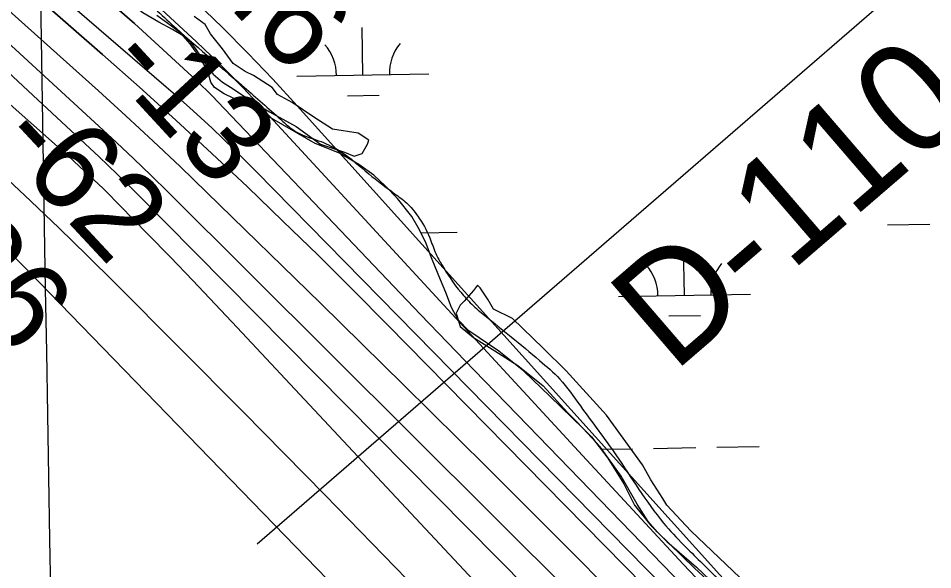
# Model space of a CAD drawing. Extents: x 3887375 to 3925618, y 296674 to 322633.
# Drawn here: x 3896776 to 3897469, y 311546 to 311964 of the extents above; entities that cross this region are included whole.
import ezdxf

# ---------------------------------------------------------------- set-up
doc = ezdxf.new("R2010")
doc.units = 0
for name, color, linetype in [('V-GRID-MAJR', 7, 'Continuous'), ('V-RIVR-EDGE', 7, 'Continuous'), ('V-RIVR-JETY', 7, 'Continuous'), ('V-RIVR-RANG', 7, 'Continuous'), ('V-RIVR-RANG-IDEN', 7, 'Continuous'), ('V-TOPO-DPTH', 7, 'Continuous'), ('V-TOPO-MAJR', 7, 'Continuous'), ('V-TOPO-MINR', 7, 'Continuous'), ('V-TOPO-WATR', 7, 'Continuous'), ('V-WETL-SWMP', 7, 'Continuous')]:
    doc.layers.add(name, color=color, linetype=linetype)

msp = doc.modelspace()

# ---------------------------------------------------------------- linework, layer by layer
at = {"layer": 'V-GRID-MAJR'}
msp.add_spline([(3896958.3310000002, 302197.087), (3896856.111, 308255.118), (3896753.858, 314315.074), (3896651.606, 320375.025), (3896651.573, 320376.956)], degree=3, dxfattribs=at)
at = {"layer": 'V-RIVR-EDGE'}
msp.add_spline([(3896115.8075614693, 312736.3390653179), (3896123.645504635, 312723.7137947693), (3896129.940618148, 312714.38723340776), (3896135.5673755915, 312703.73218250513), (3896139.52488738, 312690.4209747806), (3896139.83521988, 312681.44174761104), (3896138.156107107, 312674.7951886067), (3896136.8243285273, 312674.1334106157), (3896128.5331916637, 312683.1323720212), (3896119.587677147, 312696.45591364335), (3896111.2998293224, 312706.78500910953), (3896107.31189392, 312707.7924767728), (3896104.980870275, 312706.468098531), (3896104.302647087, 312701.14920680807), (3896107.93009214, 312688.8364218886), (3896111.2365153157, 312681.1799284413), (3896123.505720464, 312667.1830971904), (3896140.7481276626, 312647.188328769), (3896160.9586687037, 312617.2101545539), (3896188.4791912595, 312584.8861560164), (3896210.0404228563, 312563.21803064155), (3896237.5798573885, 312538.54230295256), (3896253.5077534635, 312524.8689603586), (3896271.434139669, 312512.5208182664), (3896287.7019695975, 312501.8394550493), (3896298.990841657, 312494.8282943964), (3896306.951911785, 312486.82775579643), (3896325.8306742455, 312456.1878035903), (3896335.7630999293, 312438.53885949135), (3896350.6917509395, 312424.2029166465), (3896373.5880501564, 312404.5267033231), (3896404.790286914, 312381.8371318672), (3896441.9789492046, 312359.46529324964), (3896468.8746954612, 312343.4370814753), (3896491.127306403, 312332.4083840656), (3896500.092555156, 312327.06564680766), (3896508.385336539, 312318.7317524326), (3896515.338116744, 312306.410744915), (3896528.252654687, 312284.43146478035), (3896534.8720791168, 312271.7787460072), (3896552.796820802, 312258.7655368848), (3896583.0105018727, 312239.73630087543), (3896613.555071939, 312220.041175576), (3896639.772595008, 312198.69407207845), (3896665.320939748, 312175.6859455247), (3896698.518377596, 312152.99144051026), (3896718.435853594, 312138.97569728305), (3896746.973710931, 312114.63003633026), (3896768.2056980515, 312094.2928672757), (3896793.746642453, 312068.29193908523), (3896812.6517172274, 312048.29305936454), (3896828.9006351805, 312029.9634252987), (3896844.471329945, 312006.3148995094), (3896867.3569397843, 311982.3157504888), (3896895.8898635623, 311955.9748884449), (3896948.9817541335, 311909.95370177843), (3896976.5220109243, 311885.61050760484), (3896985.1506148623, 311878.6059250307), (3896997.7729100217, 311872.9216093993), (3897005.414602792, 311870.24242930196), (3897020.0279877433, 311862.8905125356), (3897041.600730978, 311845.87785637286), (3897061.1832066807, 311830.8653348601), (3897070.144344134, 311823.8599300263), (3897078.7655477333, 311813.8625458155), (3897087.703661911, 311797.54620255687), (3897092.32952977, 311785.5634843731), (3897096.9636202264, 311776.906101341), (3897111.2115812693, 311756.25366622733), (3897119.502718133, 311747.2547048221), (3897129.4573448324, 311738.5841656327), (3897149.3698872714, 311722.5732213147), (3897170.9401637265, 311704.5629646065), (3897186.2021705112, 311690.5587330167), (3897201.7810878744, 311670.2355423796), (3897228.6250317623, 311633.25771914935), (3897264.7437346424, 311581.62539797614), (3897279.999163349, 311564.96089826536), (3897305.2100410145, 311539.95839288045), (3897328.427362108, 311515.6258880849), (3897360.94246547, 311485.9498237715), (3897388.807033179, 311458.28047218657), (3897419.340913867, 311434.2624111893), (3897433.937853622, 311420.25982411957), (3897454.4916175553, 311394.60376334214), (3897475.043736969, 311368.2826355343), (3897490.6390995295, 311354.61011520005), (3897505.558705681, 311336.61630368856), (3897515.8253093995, 311319.6316043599), (3897527.761158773, 311305.3030618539), (3897546.6736338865, 311288.2969837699), (3897564.6115317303, 311280.6043108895), (3897578.222382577, 311271.25965981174), (3897592.820966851, 311257.92213977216), (3897613.057820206, 311238.5850380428), (3897630.301049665, 311218.9228031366), (3897644.5547665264, 311200.5981026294), (3897648.867835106, 311196.59701106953), (3897654.8517938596, 311195.91714336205), (3897664.8080650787, 311187.91167120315), (3897681.400205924, 311173.90415057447), (3897695.9881008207, 311156.2436948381), (3897728.1624480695, 311123.2431176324), (3897747.7227227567, 311099.2521912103), (3897753.6811914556, 311088.26378453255), (3897756.6674150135, 311085.5961160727), (3897762.6464402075, 311082.9210472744), (3897779.5678255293, 311067.5825703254), (3897798.4712557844, 311046.91862357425), (3897815.3852407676, 311028.5873449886), (3897831.9773816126, 311014.5798243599), (3897852.225746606, 310999.8981918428), (3897867.8194646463, 310985.56060447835), (3897880.750447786, 310970.231994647), (3897893.9999860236, 310949.2494927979), (3897907.5828800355, 310928.59870220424), (3897922.1641968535, 310908.27797834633), (3897948.0310966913, 310879.615959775), (3897967.2613046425, 310856.6234561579), (3897987.8257579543, 310835.2903310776), (3898011.7139018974, 310813.2839163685), (3898048.5560522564, 310785.25983025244), (3898064.4905264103, 310774.24675578), (3898081.4127339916, 310759.240812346), (3898099.651919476, 310738.91104362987), (3898112.91790291, 310724.5792120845), (3898123.186973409, 310708.5921133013), (3898130.8048206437, 310696.2694612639), (3898136.7723342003, 310688.9389232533), (3898147.3846275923, 310677.2739379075), (3898159.9888330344, 310664.2738849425), (3898168.945036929, 310655.2732790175), (3898196.4672040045, 310623.61434751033), (3898206.0753187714, 310609.291560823), (3898214.03474438, 310600.62595519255), (3898230.2828400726, 310581.9637876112), (3898242.212933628, 310565.3075104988), (3898262.438275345, 310541.3149395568), (3898281.6758836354, 310521.3152375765), (3898296.6020678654, 310505.98169418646), (3898340.4085100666, 310470.29206976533), (3898350.024847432, 310459.2946182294), (3898356.9735163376, 310445.310943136), (3898373.552501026, 310425.98288626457), (3898390.138886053, 310409.64763102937), (3898399.4374905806, 310404.6366050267), (3898413.3808749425, 310395.29113168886), (3898421.6744785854, 310387.2897708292), (3898429.9664377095, 310378.6233429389), (3898436.5792840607, 310363.3103560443), (3898463.4437844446, 310334.64587069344), (3898482.3488592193, 310314.646990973), (3898496.60750964, 310298.31749155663), (3898513.1881388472, 310279.6545017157), (3898535.738748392, 310254.6585744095), (3898547.3461755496, 310241.9935217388), (3898560.27222513, 310224.66971081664), (3898576.512920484, 310203.01474159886), (3898592.1041717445, 310187.679553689), (3898611.3376687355, 310166.01718413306), (3898633.549988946, 310138.6943444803), (3898638.1947687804, 310134.3598971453), (3898642.5144154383, 310133.0190737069), (3898652.1447312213, 310127.67469192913), (3898657.787933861, 310123.6703113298), (3898665.4164704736, 310115.6705949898), (3898676.6880750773, 310101.6762305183), (3898685.971878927, 310090.6796012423), (3898692.6093930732, 310085.342619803), (3898699.247729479, 310080.33817187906), (3898707.868110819, 310070.008254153), (3898714.4850684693, 310056.3579348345), (3898718.4442247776, 310043.7117941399), (3898720.43284779, 310041.04659245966), (3898727.404539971, 310036.3738557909), (3898760.272733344, 310015.0103070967), (3898774.2169399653, 310005.9973672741), (3898785.4943003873, 309994.3307374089), (3898801.4041067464, 309973.3416574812), (3898808.685309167, 309959.3571601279), (3898822.609781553, 309942.36341594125), (3898837.8627434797, 309924.70131568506), (3898844.8253908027, 309916.37071034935), (3898858.7490409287, 309899.04443264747), (3898871.351601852, 309885.3793126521), (3898894.5426106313, 309850.4057353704), (3898899.8541020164, 309846.7347105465), (3898908.4851727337, 309840.7277285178), (3898917.1244660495, 309838.0460816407), (3898920.4440453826, 309835.71012443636), (3898928.060248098, 309822.7224053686), (3898935.3513176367, 309812.7283101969), (3898943.639987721, 309802.7317482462), (3898951.916323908, 309787.747183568), (3898962.852105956, 309772.4235072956), (3898972.4585762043, 309757.4356535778), (3898979.0969126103, 309752.4312056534), (3898987.0694943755, 309749.08613626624), (3898990.7174959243, 309745.0866892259), (3899001.9808779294, 309727.76698960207), (3899013.2565938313, 309715.4352927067), (3899031.16653484, 309696.43648031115), (3899044.7601182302, 309680.1086254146), (3899055.6975447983, 309665.4500161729), (3899064.9797041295, 309653.78831986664), (3899074.589463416, 309640.13060020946), (3899085.5400461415, 309630.79252721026), (3899093.846805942, 309628.11170259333), (3899099.1673421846, 309628.09854643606), (3899103.152810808, 309626.09347822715), (3899108.1161457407, 309616.1051388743), (3899114.7429705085, 309606.44522173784), (3899123.683551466, 309591.1264790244), (3899128.318464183, 309582.8016295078), (3899128.3127083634, 309580.47389490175), (3899127.6196844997, 309569.1693999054), (3899127.9439954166, 309565.84324249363), (3899132.921308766, 309561.5079728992), (3899159.7767642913, 309529.18561888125), (3899190.9559777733, 309497.18510900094), (3899204.881272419, 309480.52389832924), (3899212.171519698, 309470.19726964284), (3899224.775725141, 309457.19721667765), (3899244.679222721, 309437.5284036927), (3899252.6411151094, 309429.86039860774), (3899261.9347860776, 309422.8541715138), (3899272.5585911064, 309415.84465538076), (3899279.51877165, 309406.5164494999), (3899287.4740859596, 309396.18817629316), (3899300.0618462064, 309376.5374530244), (3899311.333450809, 309362.5430885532), (3899327.912435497, 309343.21503168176), (3899342.167796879, 309325.55539820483), (3899360.0728043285, 309304.56138471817), (3899377.311100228, 309282.9039487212), (3899414.4504269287, 309240.5800991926), (3899433.3530349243, 309219.5836189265), (3899447.280796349, 309203.92000880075), (3899464.5256703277, 309184.92284092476), (3899479.112742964, 309166.92985167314), (3899493.3697488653, 309149.9352852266)], degree=3, dxfattribs=at)
at = {"layer": 'V-RIVR-JETY'}
for points in [[(3896881.043411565, 311966.0012621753), (3896892.2221385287, 311957.871278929), (3896900.352121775, 311951.7737914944), (3896906.4496092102, 311945.6763040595), (3896910.514600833, 311940.5950645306), (3896917.6283361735, 311929.41633756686), (3896923.7258236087, 311921.28635432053), (3896930.8395589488, 311915.1888668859), (3896938.9695421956, 311910.107627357), (3896951.1645170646, 311901.9776441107), (3896966.4082356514, 311892.8314129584), (3896986.7331937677, 311881.65268599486), (3897005.025656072, 311868.44146321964), (3897023.3181183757, 311862.3439757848), (3897030.431853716, 311859.29523206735), (3897036.5293411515, 311861.32772787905), (3897040.594332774, 311868.44146321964), (3897041.61058068, 311871.49020693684), (3897033.4805974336, 311876.57144646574), (3897014.171887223, 311879.62019018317), (3896999.9444165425, 311888.7664213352), (3896983.68445005, 311899.945148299), (3896972.5057230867, 311906.04263573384), (3896968.440731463, 311911.12387526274), (3896954.2132607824, 311920.2701064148), (3896948.115773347, 311923.31885013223), (3896938.9695421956, 311929.41633756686), (3896930.8395589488, 311940.5950645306), (3896921.693327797, 311951.7737914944), (3896917.6283361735, 311958.88752683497), (3896909.498352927, 311964.9850142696)], [(3897333.2737296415, 311530.03091059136), (3897285.5100780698, 311575.7620663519), (3897267.217615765, 311595.070776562), (3897264.168872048, 311600.15201609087), (3897255.022640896, 311614.3794867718), (3897248.9251534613, 311625.5582137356), (3897221.486460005, 311663.1593862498), (3897190.999022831, 311696.6955671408), (3897173.7228084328, 311713.97178153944), (3897150.3491065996, 311736.3292354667), (3897136.121635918, 311743.4429708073), (3897132.056644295, 311750.5567061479), (3897125.9591568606, 311759.70293729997), (3897123.926661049, 311761.73543311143), (3897120.8779173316, 311757.67044148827), (3897113.7641819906, 311749.54045824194), (3897110.7154382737, 311746.49171452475), (3897107.6666945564, 311740.3942270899), (3897110.7154382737, 311730.2317480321), (3897120.8779173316, 311722.10176478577), (3897137.1378838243, 311711.93928572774), (3897154.4140982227, 311700.760558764), (3897173.7228084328, 311685.5168401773), (3897192.015270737, 311665.1918820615), (3897210.307733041, 311646.89941975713), (3897222.5027079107, 311630.6394532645), (3897234.6976827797, 311611.3307430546), (3897242.827666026, 311595.070776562), (3897255.022640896, 311579.82705797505), (3897267.217615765, 311567.63208310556), (3897289.575069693, 311548.3233728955), (3897309.9000278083, 311529.01466268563)]]:
    msp.add_lwpolyline(points, dxfattribs=at)
at = {"layer": 'V-RIVR-RANG'}
msp.add_line((3897501.5199, 312036.84659999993), (3896957.1909, 311565.5654000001), dxfattribs=at)
at = {"layer": 'V-TOPO-DPTH'}
for points in [[(3897420.1434630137, 311417.2895414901), (3896987.428998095, 311897.46273339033), (3896968.9094085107, 311917.5150554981), (3896950.071898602, 311937.25650301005), (3896930.7575082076, 311956.5316386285), (3896911.125197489, 311975.4958996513), (3896659.026278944, 312213.12816606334)], [(3896546.070862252, 312192.99895366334), (3896840.0793984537, 311936.0956112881), (3896867.8900182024, 311911.4736937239), (3896895.4833059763, 311886.61368441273), (3896922.7505957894, 311861.3965374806), (3896949.8005536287, 311835.94129880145), (3896976.5613031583, 311810.17931244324), (3897003.153895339, 311784.2465513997), (3897029.4942514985, 311758.05762832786), (3897055.66645031, 311731.69793057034), (3897384.504321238, 311397.2828174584)], [(3896546.070862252, 312192.99895366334), (3896840.0793984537, 311936.0956112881), (3896867.8900182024, 311911.4736937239), (3896895.4833059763, 311886.61368441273), (3896922.7505957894, 311861.3965374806), (3896949.8005536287, 311835.94129880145), (3896976.5613031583, 311810.17931244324), (3897003.153895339, 311784.2465513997), (3897029.4942514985, 311758.05762832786), (3897055.66645031, 311731.69793057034), (3897384.504321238, 311397.2828174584)], [(3897412.9777930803, 311396.37510842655), (3897162.005666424, 311655.33049372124), (3897121.360767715, 311697.3852875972), (3897080.7941851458, 311739.5152815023), (3897040.3450767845, 311781.7580754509), (3896999.974284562, 311824.07606942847), (3896927.37578062, 311900.38867008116), (3896923.32426325, 311904.5675344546), (3896919.2211682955, 311908.69413510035), (3896915.040706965, 311912.7423401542), (3896910.808668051, 311916.7382814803), (3896882.6488346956, 311942.8274258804), (3896864.1276609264, 311959.63134587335), (3896845.3793784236, 311976.1723793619), (3896826.2904328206, 311992.3190830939), (3896806.974378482, 312008.20290032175), (3896718.119793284, 312079.7298174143)], [(3896718.119793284, 312079.7298174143), (3896806.974378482, 312008.20290032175), (3896826.2904328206, 311992.3190830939), (3896845.3793784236, 311976.1723793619), (3896864.1276609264, 311959.63134587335), (3896882.6488346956, 311942.8274258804), (3896910.808668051, 311916.7382814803), (3896915.040706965, 311912.7423401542), (3896919.2211682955, 311908.69413510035), (3896923.32426325, 311904.5675344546), (3896927.37578062, 311900.38867008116), (3896999.974284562, 311824.07606942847), (3897040.3450767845, 311781.7580754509), (3897080.7941851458, 311739.5152815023), (3897121.360767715, 311697.3852875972), (3897162.005666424, 311655.33049372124), (3897412.9777930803, 311396.37510842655)], [(3897255.0818033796, 311499.3240481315), (3897192.9470212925, 311561.8939687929), (3897130.583000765, 311624.2332881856), (3897067.875122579, 311686.2267056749), (3897004.938005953, 311747.98952189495), (3896918.9797630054, 311831.8785189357), (3896898.728047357, 311851.39369997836), (3896878.3140194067, 311870.73538092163), (3896857.6565230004, 311889.81681171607), (3896836.836714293, 311908.72474241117), (3896671.849378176, 312056.66443618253)], [(3896671.849378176, 312056.66443618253), (3896836.836714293, 311908.72474241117), (3896857.6565230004, 311889.81681171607), (3896878.3140194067, 311870.73538092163), (3896898.728047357, 311851.39369997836), (3896918.9797630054, 311831.8785189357), (3897004.938005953, 311747.98952189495), (3897067.875122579, 311686.2267056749), (3897130.583000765, 311624.2332881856), (3897192.9470212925, 311561.8939687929), (3897255.0818033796, 311499.3240481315)], [(3897197.703189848, 311525.55908283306), (3896889.6358889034, 311832.0078495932), (3896876.7361088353, 311844.6822550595), (3896863.7334744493, 311857.24891363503), (3896850.576558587, 311869.653951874), (3896837.316788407, 311881.95124322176), (3896755.066131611, 311957.29171772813)], [(3896755.066131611, 311957.29171772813), (3896837.316788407, 311881.95124322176), (3896850.576558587, 311869.653951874), (3896863.7334744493, 311857.24891363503), (3896876.7361088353, 311844.6822550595), (3896889.6358889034, 311832.0078495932), (3897197.703189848, 311525.55908283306)]]:
    msp.add_lwpolyline(points, dxfattribs=at)
at = {"layer": 'V-TOPO-MAJR'}
msp.add_lwpolyline([(3897253.0924748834, 311439.79355773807), (3896864.6019191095, 311832.3439709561), (3896857.9176288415, 311839.0152375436), (3896851.1792346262, 311845.63071009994), (3896844.3596844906, 311852.1624916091), (3896837.486030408, 311858.6384790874), (3896790.9928980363, 311901.90316933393), (3896760.727256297, 311929.8540996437)], dxfattribs=at)
at = {"layer": 'V-TOPO-MINR'}
for points in [[(3897314.540538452, 311331.60939022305), (3896942.069907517, 311729.50638343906), (3896925.266709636, 311747.3355020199), (3896908.3837895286, 311765.08829002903), (3896891.381286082, 311782.72658218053), (3896874.2990604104, 311800.28854376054), (3896842.4523561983, 311832.80904753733), (3896839.987715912, 311835.2700006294), (3896837.468495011, 311837.67505113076), (3896828.754836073, 311845.80896961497), (3896823.1051535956, 311851.042947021), (3896817.4293492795, 311856.24822432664), (3896811.714362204, 311861.4104514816), (3896805.9732532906, 311866.5439785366), (3896332.2399523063, 312286.93091264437)], [(3897398.8809638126, 311396.79180321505), (3896956.268622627, 311847.7749467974), (3896948.048482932, 311856.0502641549), (3896939.7628381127, 311864.25865863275), (3896931.3789356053, 311872.3666687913), (3896922.929527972, 311880.40775607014), (3896914.379513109, 311888.34143411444), (3896905.7609100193, 311896.1988759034), (3896897.0394245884, 311903.9419633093), (3896888.249350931, 311911.6088144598), (3896483.926541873, 312259.5976252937)], [(3897384.504321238, 311397.2828174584), (3897055.66645031, 311731.69793057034), (3897029.4942514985, 311758.05762832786), (3897003.153895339, 311784.2465513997), (3896976.5613031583, 311810.17931244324), (3896949.8005536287, 311835.94129880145), (3896922.7505957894, 311861.3965374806), (3896895.4833059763, 311886.61368441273), (3896867.8900182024, 311911.4736937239), (3896840.0793984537, 311936.0956112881), (3896546.070862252, 312192.99895366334)], [(3897412.9777930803, 311396.37510842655), (3897162.005666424, 311655.33049372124), (3897121.360767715, 311697.3852875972), (3897080.7941851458, 311739.5152815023), (3897040.3450767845, 311781.7580754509), (3896999.974284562, 311824.07606942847), (3896927.37578062, 311900.38867008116), (3896923.32426325, 311904.5675344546), (3896919.2211682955, 311908.69413510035), (3896915.040706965, 311912.7423401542), (3896910.808668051, 311916.7382814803), (3896882.6488346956, 311942.8274258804), (3896864.1276609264, 311959.63134587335), (3896845.3793784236, 311976.1723793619), (3896826.2904328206, 311992.3190830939), (3896806.974378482, 312008.20290032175), (3896718.119793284, 312079.7298174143)], [(3897318.134412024, 311509.82452472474), (3897279.666263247, 311550.5721031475), (3897241.417704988, 311591.5258747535), (3897203.315540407, 311632.6171084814), (3896957.5679034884, 311899.07622020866), (3896946.2021966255, 311911.1173004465), (3896934.65565846, 311922.97822240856), (3896922.8378733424, 311934.5689069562), (3896910.839256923, 311945.979433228), (3896829.506172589, 312021.5537884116), (3896776.1276084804, 312069.94098790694)], [(3897255.0818033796, 311499.3240481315), (3897192.9470212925, 311561.8939687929), (3897130.583000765, 311624.2332881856), (3897067.875122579, 311686.2267056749), (3897004.938005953, 311747.98952189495), (3896918.9797630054, 311831.8785189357), (3896898.728047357, 311851.39369997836), (3896878.3140194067, 311870.73538092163), (3896857.6565230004, 311889.81681171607), (3896836.836714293, 311908.72474241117), (3896671.849378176, 312056.66443618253)], [(3897197.703189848, 311525.55908283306), (3896889.6358889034, 311832.0078495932), (3896876.7361088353, 311844.6822550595), (3896863.7334744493, 311857.24891363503), (3896850.576558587, 311869.653951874), (3896837.316788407, 311881.95124322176), (3896755.066131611, 311957.29171772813)], [(3897070.393817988, 311539.2438048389), (3897008.537605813, 311602.590176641), (3896946.3761133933, 311665.6405900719), (3896849.5078773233, 311763.1887739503), (3896828.4556274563, 311784.1168297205), (3896807.226014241, 311804.8610119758), (3896785.730356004, 311825.3293839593), (3896764.057334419, 311845.61388242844)], [(3897018.3656231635, 311530.44390751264), (3896791.8293534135, 311764.21580990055), (3896785.041337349, 311771.1335805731), (3896778.1965041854, 311777.99394968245), (3896771.2664453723, 311784.76821644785)]]:
    msp.add_lwpolyline(points, dxfattribs=at)
at = {"layer": 'V-TOPO-WATR'}
msp.add_lwpolyline([(3897420.1434630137, 311417.2895414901), (3896987.428998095, 311897.46273339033), (3896968.9094085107, 311917.5150554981), (3896950.071898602, 311937.25650301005), (3896930.7575082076, 311956.5316386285), (3896911.125197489, 311975.4958996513), (3896659.026278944, 312213.12816606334)], dxfattribs=at)
at = {"layer": 'V-WETL-SWMP'}
for p, q in [((3897037.173210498, 311920.63683151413), (3897036.5553735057, 311956.63152718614)), ((3896987.180578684, 311919.7787319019), (3897087.165842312, 311921.49493112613)), ((3897025.4398078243, 311905.00216124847), (3897049.4362710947, 311905.41404906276)), ((3897434.23966755, 311807.3636083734), (3897466.234951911, 311807.91279212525)), ((3897081.0424600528, 311801.3011472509), (3897108.3796945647, 311801.7703778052)), ((3897280.541290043, 311753.9759781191), (3897279.9234530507, 311789.97067379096)), ((3897230.548658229, 311753.1178785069), (3897330.533921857, 311754.83407773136)), ((3897268.8078873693, 311738.34130785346), (3897292.8043506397, 311738.7531956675)), ((3897217.964126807, 311637.45287513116), (3897241.120452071, 311637.8503423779)), ((3897257.1180942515, 311638.1249342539), (3897289.113378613, 311638.6741180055)), ((3897305.111020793, 311638.9487098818), (3897337.106305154, 311639.4978936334))]:
    msp.add_line(p, q, dxfattribs=at)
for points in [[(3896939.008, 311903.206), (3896932.019, 311906.346), (3896924.8200000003, 311911.276), (3896922.007, 311915.24), (3896919.361, 311923.982), (3896913.9220000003, 311933.702), (3896906.287, 311944.403), (3896901.072, 311950.342), (3896893.077, 311955.068), (3896882.687, 311960.773), (3896870.498, 311967.662), (3896864.693, 311972.402), (3896854.051, 311986.26900000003), (3896846.005, 311998.759), (3896840.568, 312008.28), (3896828.338, 312021.34), (3896816.919, 312032.215), (3896804.288, 312045.67100000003), (3896798.461, 312053.795), (3896788.19, 312071.84500000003), (3896783.762, 312079.183), (3896776.931, 312088.694), (3896769.311, 312097.006)], [(3897376.6780000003, 311466.078), (3897288.149, 311547.325), (3897259.897, 311575.01300000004), (3897253.077, 311582.733), (3897244.829, 311595.819), (3897232.745, 311617.043), (3897216.673, 311639.23600000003), (3897203.84, 311653.088), (3897178.595, 311677.61), (3897158.96, 311696.59500000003), (3897139.947, 311711.8), (3897117.35, 311726.983), (3897109.132, 311735.49), (3897104.294, 311744.616), (3897099.839, 311756.134), (3897095.994, 311765.666), (3897089.523, 311780.953), (3897084.457, 311794.458), (3897079.011, 311805.373), (3897074.1780000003, 311813.703), (3897063.339, 311827.17), (3897054.318, 311836.667), (3897045.306, 311844.771), (3897034.103, 311853.06), (3897019.315, 311861.52400000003), (3897000.95, 311868.969), (3896963.379, 311890.624), (3896939.008, 311903.206)]]:
    msp.add_lwpolyline(points, dxfattribs=at)
for centre, radius, start, end in [((3896981.9302665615, 311920.16348589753), 35.24628790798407, 0.2115380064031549, 41.755196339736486), ((3897092.399857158, 311922.0596435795), 35.24628790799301, 140.21153503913, 181.75519337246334), ((3897225.298346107, 311753.5026325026), 35.24628790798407, 0.2115380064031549, 41.755196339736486), ((3897335.767936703, 311755.3987901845), 35.24628790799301, 140.21153503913, 181.75519337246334)]:
    msp.add_arc(centre, radius, start, end, dxfattribs=at)

# ---------------------------------------------------------------- texts
at = {"layer": 'V-RIVR-RANG'}
for s, height, rotation, p in [('3.6', 67.00000000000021, 312.67832571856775, (3896900.3342312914, 312010.3625056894)), ('-13', 67.00000000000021, 312.67832571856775, (3896840.222266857, 311928.03619772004)), ('-62', 67.00000000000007, 312.96630555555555, (3896757.7536160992, 311869.3571885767)), ('-86', 67.00000000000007, 312.96630555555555, (3896685.4893184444, 311800.2230572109))]:
    msp.add_text(s, height=height, rotation=rotation, dxfattribs=at).set_placement(p)
at = {"layer": 'V-RIVR-RANG-IDEN'}
msp.add_text('D-110', height=83.00000000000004, rotation=40.74432571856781, dxfattribs=at).set_placement((3897272.171026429, 311694.75135911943))

doc.saveas('drawing.dxf')
